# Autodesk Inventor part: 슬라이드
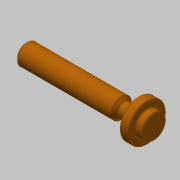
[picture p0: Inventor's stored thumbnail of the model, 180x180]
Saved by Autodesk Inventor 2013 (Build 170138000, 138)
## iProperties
Company: 한국ATC센터
Created: 2015-12
Part Number: 슬라이드
Document SubType Name: Modeling
Designer: mdu
Density: 7.86 g/cm^3
Mass: 68.0563 g
Surface Area: 34.7349 cm^2
Volume: 8.65856 cm^3
Material: 강철, 연강
Author: mdu
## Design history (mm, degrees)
sketch "스케치1"
  geometry: L1 (-35, 0)-(35, 0); L2 (35, 0)-(35, 11); L3 (35, 11)-(30, 11); L4 (30, 11)-(30, 4); L5 (30, 4)-(22, 4); L6 (22, 4)-(20, 6); L7 (20, 6)-(-35, 6); L8 (-35, 6)-(-35, 0); 1 further point
  constraints: 16 end point, 4 parallel, 2 midpoint, 2 perpendicular, 1 horizontal
  dimensions: "d0" = 70 distance of L1.start L1.end; "d1" = 12 diameter of L7 L1; "d2" = 22 diameter of L3 L1; "d3" = 5 distance of L2.end L3.end; "d4" = 8 diameter of L5 L1; "d5" = 135 deg angle of L6 L5; "d6" = 15 distance from line of L2 L6.end
revolve "회전1" sketch "스케치1" stored, may be unused: angle "d7" = 90 deg
chamfer "모따기1" distance "d8" = 1; stored, may be unused: second distance "d9" = 2, angle "d10" = 45 deg
fillet "모깎기1" dims "d11" = 0.5
sketch "스케치5"
  geometry: C1 r 7 at (0, 0); 1 further point
  constraints: 1 centre point, 1 coincident
  dimensions: "d23" = 14 diameter of C1
extrude "돌출2" join sketch "스케치5" distance "d24" = 4; taper "d25" = 0 deg
fillet "모깎기3" dims "d26" = 0.5
node "솔리드1"
